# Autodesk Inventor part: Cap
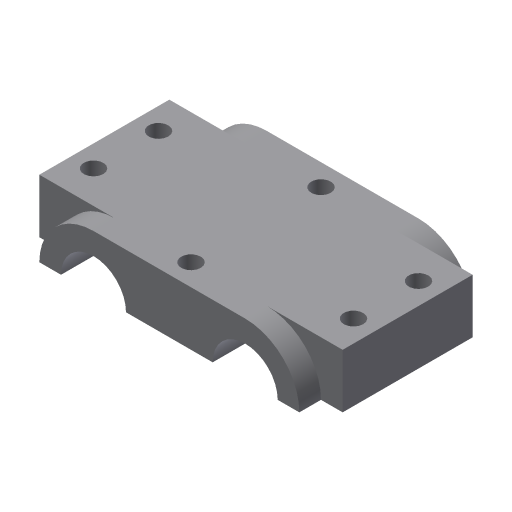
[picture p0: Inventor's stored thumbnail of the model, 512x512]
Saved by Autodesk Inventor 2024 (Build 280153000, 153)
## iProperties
Shininess: 77.0
Length Units: 11269
Angle Units: 11279
Time Units: 11290
Mass Units: 11283
Length Display Precision: 3
Angle Display Precision: 2
Created: 2002-02
Part Number: Cap
Document SubType Name: Modeling
Designer: ***
Density: 1 g/cm^3
Material: Generic
Appearance: Default
Density: 0.0
Volumn: 0.0
Area: 0.0
PropertySet Name: Model Information
Control State: 0
Master: False
Checked Out: False
Author: ***
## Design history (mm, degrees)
sketch "Sketch2"
  geometry: L1 (-17.5, 12.5)-(17.5, 12.5); L2 (30, 0)-(25, 0); L3 (10, 0)-(-10, 0); L4 (-25, 0)-(-30, 0); A1 r 12.5 centre (-17.5, 0) between (-17.5, 12.5) and (-30, 0); A2 r 12.5 centre (17.5, 0) between (30, 0) and (17.5, 12.5); A3 r 7.5 centre (17.5, 0) between (25, 0) and (10, 0); A4 r 7.5 centre (-17.5, 0) between (-10, 0) and (-25, 0)
  constraints: 8 end point, 8 point on circle, 4 centre point, 3 horizontal, 3 parallel, 2 coincident, 2 equal radius, 2 tangent
  dimensions: "d0" = 12.5 radius of A1; "d1" = 7.5 radius of A4; "d2" = 35 distance of A1.centre A2.centre; "d3" = 12.5 distance between parallel lines of L1 L3
extrude "Extrusion1" new body sketch "Sketch2" stored distance "d4" = 40; taper "d5" = 0 deg
workplane "Work Plane1"
sketch "Sketch3"
  geometry: L1 (-15, 12.5)-(15, 12.5); L2 (15, 12.5)-(15, 0); L3 (15, 0)-(-15, 0); L4 (-15, 0)-(-15, 12.5); L5 (-20, 0)-(20, 0) reference; L6 (-20, 12.5)-(20, 12.5) reference; L7 (20, 12.5)-(20, 0) reference
  constraints: 8 end point, 2 collinear, 2 parallel, 1 horizontal, 1 perpendicular
  dimensions: "d7" = 30 distance of L2.end L3.end; "d8" = 5 distance between parallel lines of L7 L2
extrude "Extrusion2" join sketch "Sketch3" stored distance "d9" = 40; taper "d10" = 0 deg
mirror "Mirror1"
sketch "Sketch4"
  geometry: L1 (-17.5, -35)-(0, -35) reference; L2 (-17.5, -35)-(-17.5, -5) reference; 1 further point
  dimensions: "d12" = 7.5 distance from line of L1 point (-12.5, -27.5); "d13" = 5 distance from line of L2 point (-12.5, -27.5)
hole "Hole1" sketch "Sketch4" diameter "d14" = 4.5; stored, may be unused: countersink angle "d18" = 82 deg, drill point angle "d20" = 118 deg; dims "d15" = 6, "d16" = 4, "d17" = 2, "d19" = 8
pattern_linear "Rectangular Pattern1" dims "d23" = 60, "d26" = 15
sketch "Sketch5"
  geometry: L1 (0, -40)-(35, -40) reference; L2 (-17.5, -35)-(-17.5, -5) reference; 1 further point
  dimensions: "d27" = 5 distance from line of L1 point (17.5, -35); "d28" = 35 distance from line of L2 point (17.5, -35)
hole "Hole2" sketch "Sketch5" diameter "d29" = 4.5; stored, may be unused: countersink angle "d33" = 82 deg, drill point angle "d35" = 118 deg; dims "d30" = 6, "d31" = 4, "d32" = 2, "d34" = 8
pattern_linear "Rectangular Pattern2" dims "d38" = 30
body "Solid1"
other parameters: "d11" = 35
